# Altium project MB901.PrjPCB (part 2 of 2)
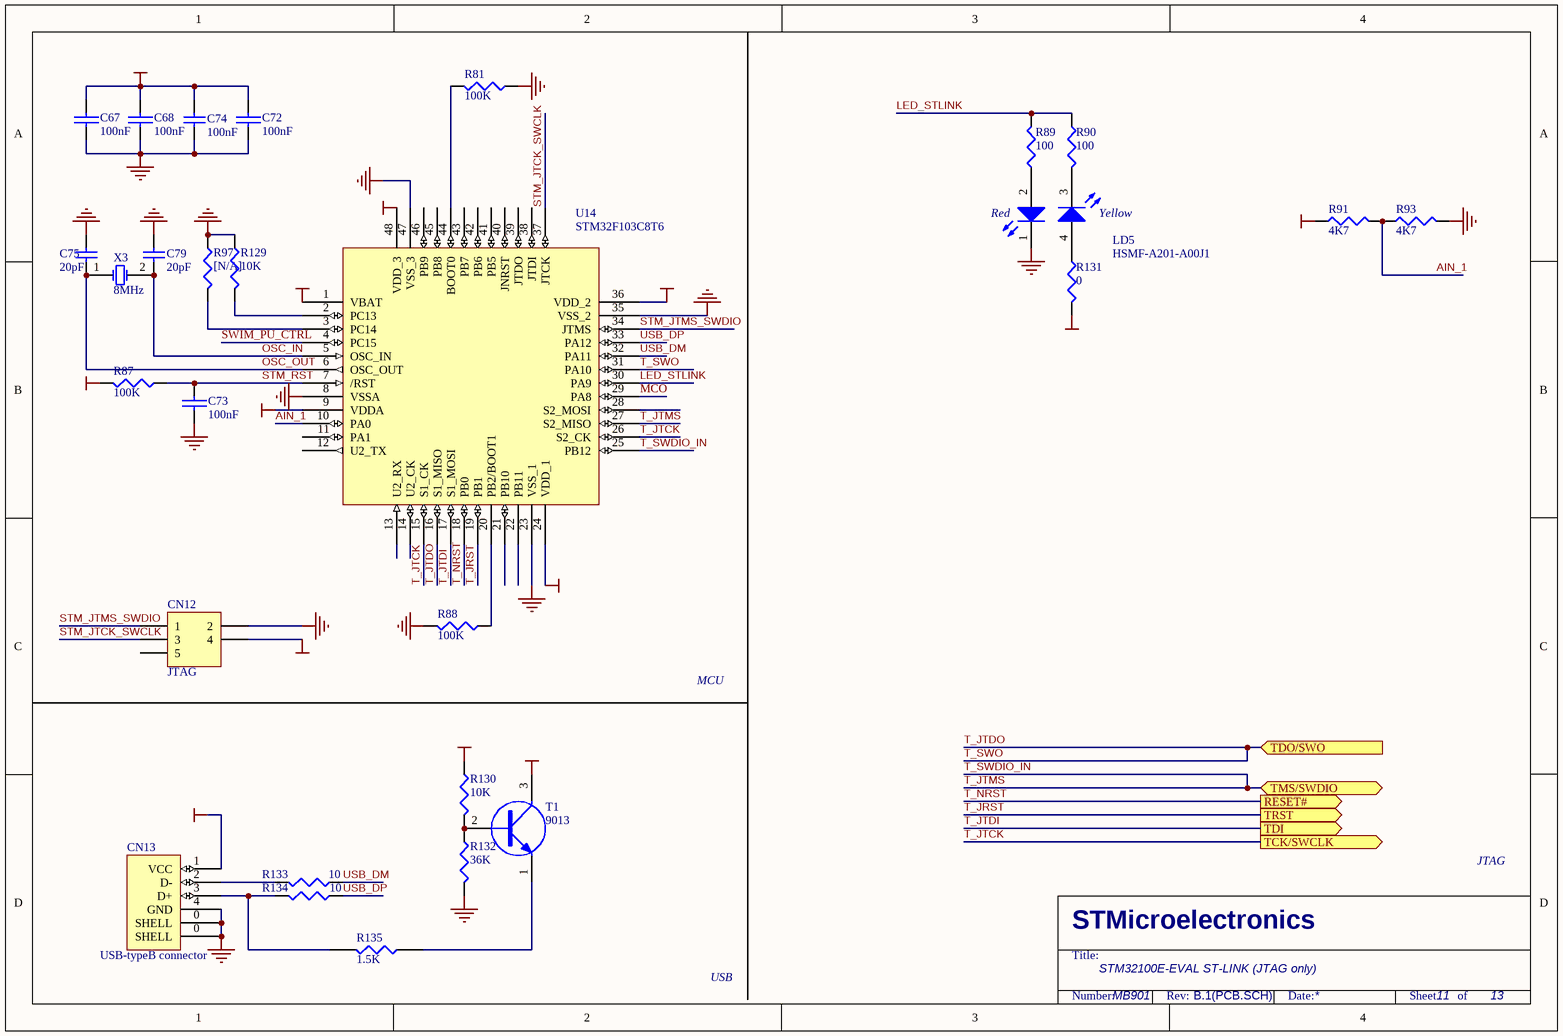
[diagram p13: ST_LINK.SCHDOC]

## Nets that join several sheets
+3V3: MB901 (R83.1 R112.1), Audio (C61.1 R82.1 U11.E3), CEC&IR receiver (7 pins), IO_Peripheral (11 pins), JTAG&SWD (7 pins), LCD&EEPROM&TS (18 pins), MCU (6 pins), MicroSD&SPIFlash (7 pins), MotorCtrl (CN1.28 R10.2), Power (6 pins), RS232&IrDA (13 pins), SRAM&OneNAND (14 pins), ST_LINK (14 pins)
+5V: Audio (C60.1 C62.1 U11.C3 U11.C5), CEC&IR receiver (C20.1 U2.6), LCD&EEPROM&TS (R136.1), MotorCtrl (CN1.25), Power (7 pins), RS232&IrDA (R55.2 U9.8)
D5V: MCU (CN8.49 CN9.19), Power (JP13.4)
GND: Audio (8 pins), CEC&IR receiver (19 pins), IO_Peripheral (26 pins), JTAG&SWD (19 pins), LCD&EEPROM&TS (18 pins), MCU (24 pins), MicroSD&SPIFlash (8 pins), MotorCtrl (27 pins), Power (39 pins), RS232&IrDA (22 pins), SRAM&OneNAND (13 pins), ST_LINK (21 pins)
U5V_ST_LINK: Power (JP13.2), ST_LINK (CN13.1 R130.1)
A0: LCD&EEPROM&TS (CN15.2), MCU (CN8.57 U8.10), SRAM&OneNAND (U3.A3 U4.G2)
A1: MCU (CN8.60 U8.11), SRAM&OneNAND (U3.A4 U4.G3)
A2: MCU (CN8.61 U8.12), SRAM&OneNAND (U3.A5 U4.H4)
A3: MCU (CN8.62 U8.13), SRAM&OneNAND (U3.B3 U4.H5)
A4: MCU (CN8.63 U8.14), SRAM&OneNAND (U3.B4 U4.H2)
A5: MCU (CN8.64 U8.15), SRAM&OneNAND (U3.C3 U4.H3)
A6: MCU (CN9.43 U8.50), SRAM&OneNAND (U3.C4 U4.G6)
A7: MCU (CN9.44 U8.53), SRAM&OneNAND (U3.D4 U4.F4)
A8: MCU (CN9.41 U8.54), SRAM&OneNAND (U3.H2 U4.F6)
A9: MCU (CN9.42 U8.55), SRAM&OneNAND (U3.H3 U4.E6)
A10: MCU (CN9.40 U8.56), SRAM&OneNAND (U3.H4 U4.G5)
A11: MCU (CN9.37 U8.57), SRAM&OneNAND (U3.H5 U4.F5)
A12: MCU (CN9.8 U8.87), SRAM&OneNAND (U3.G3 U4.D2)
A13: MCU (CN9.7 U8.88), SRAM&OneNAND (U3.G4 U4.F2)
A14: MCU (CN9.6 U8.89), SRAM&OneNAND (U3.F3 U4.F1)
A15: MCU (CN9.5 U8.90), SRAM&OneNAND (U3.F4 U4.D4)
A16: MCU (CN9.14 U8.80), SRAM&OneNAND (U3.E4)
A17: MCU (CN9.13 U8.81), SRAM&OneNAND (U3.D3)
A18: MCU (CN9.12 U8.82), SRAM&OneNAND (U3.H1)
A19: MCU (CN8.52 U8.2), SRAM&OneNAND (U3.G2)
A20: MCU (CN8.51 U8.3), SRAM&OneNAND (U3.H6)
D0: LCD&EEPROM&TS (CN15.6), MCU (CN9.32 U8.85), SRAM&OneNAND (U3.B6 U4.D3)
D1: LCD&EEPROM&TS (CN15.7), MCU (CN9.31 U8.86), SRAM&OneNAND (U3.C5 U4.B3)
D2: LCD&EEPROM&TS (CN15.8), MCU (CN8.21 U8.114), SRAM&OneNAND (U3.C6 U4.E3)
D3: LCD&EEPROM&TS (CN15.9), MCU (CN8.22 U8.115), SRAM&OneNAND (U3.D5 U4.C5)
D4: LCD&EEPROM&TS (CN15.10), MCU (CN9.35 U8.58), SRAM&OneNAND (U3.E5 U4.C2)
D5: LCD&EEPROM&TS (CN15.11), MCU (CN9.36 U8.59), SRAM&OneNAND (U3.F5 U4.D5)
D6: LCD&EEPROM&TS (CN15.12), MCU (CN9.33 U8.60), SRAM&OneNAND (U3.F6 U4.D6)
D7: LCD&EEPROM&TS (CN15.13), MCU (CN9.34 U8.63), SRAM&OneNAND (U3.G6 U4.C1)
D8: LCD&EEPROM&TS (CN15.14), MCU (CN9.29 U8.64), SRAM&OneNAND (U3.B1 U4.B2)
D9: LCD&EEPROM&TS (CN15.15), MCU (CN9.28 U8.65), SRAM&OneNAND (U3.C1 U4.B5)
D10: LCD&EEPROM&TS (CN15.16), MCU (CN9.27 U8.66), SRAM&OneNAND (U3.C2 U4.C4)
D11: LCD&EEPROM&TS (CN15.17), MCU (CN9.26 U8.67), SRAM&OneNAND (U3.D2 U4.C3)
D12: LCD&EEPROM&TS (CN15.18), MCU (CN9.25 U8.68), SRAM&OneNAND (U3.E2 U4.B1)
D13: LCD&EEPROM&TS (CN15.19), MCU (CN9.17 U8.77), SRAM&OneNAND (U3.F2 U4.A6)
D14: LCD&EEPROM&TS (CN15.20), MCU (CN9.16 U8.78), SRAM&OneNAND (U3.F1 U4.A3)
D15: LCD&EEPROM&TS (CN15.21), MCU (CN9.15 U8.79), SRAM&OneNAND (U3.G1 U4.D1)
NetC13_2: MCU (JP4.1), MotorCtrl (C13.2 CN1.31 JP2.1)
NetCN1_11: MCU (JP5.3), MotorCtrl (CN1.11)
NetCN11_5: Audio (CN11.5), LCD&EEPROM&TS (U19.11)
NetJP3_2: MCU (JP3.2), MotorCtrl (R8.2)
NetJP4_3: MCU (JP4.3), RS232&IrDA (R33.2)
NetJP5_1: MCU (JP5.1), RS232&IrDA (R43.2)
NetJP6_1: MCU (JP6.1), SRAM&OneNAND (U4.F3)
NetJP6_3: CEC&IR receiver (R39.2), MCU (JP6.3)
NetJP7_2: MCU (JP7.2), RS232&IrDA (U7.16)
NetJP8_2: MCU (JP8.2), RS232&IrDA (U7.20)
NetJP9_1: MCU (JP9.1), RS232&IrDA (R66.2)
NetJP11_2: LCD&EEPROM&TS (R78.1), MCU (JP11.2)
NetR72_1: MB901 (R72.1 R112.2), Audio (U11.E5), LCD&EEPROM&TS (U10.1 U13.5 U19.5)
NetR77_1: MB901 (R77.1 R83.2), Audio (U11.E1), LCD&EEPROM&TS (U10.2 U13.6 U19.4)
PA0: IO_Peripheral (R101.2), MCU (CN8.9 JP4.2 U8.34)
PA1: MCU (CN9.61 U8.35), MotorCtrl (C4.2 CN1.33), RS232&IrDA (R27.2 U5.10)
PA2: MCU (CN9.60 U8.36), MotorCtrl (C5.2 CN1.34), RS232&IrDA (R31.2 U5.11)
PA3: MCU (CN9.58 U8.37), RS232&IrDA (R138.2)
PA4: Audio (C64.2 C66.2), IO_Peripheral (R48.1), MCU (CN9.57 U8.40)
PA5: Audio (JP15.2), MCU (CN9.56 U8.41), MicroSD&SPIFlash (U6.6)
PA6: MCU (CN9.55 JP3.1 U8.42), MicroSD&SPIFlash (R46.1)
PA7: MCU (CN9.54 U8.43), MicroSD&SPIFlash (U6.5), MotorCtrl (CN1.5)
PA8: MCU (CN8.6 TP6.1 U8.100), MotorCtrl (CN1.3)
PA9: MCU (CN8.7 U8.101), MotorCtrl (CN1.7), RS232&IrDA (R50.2 U7.13)
PA11: MCU (CN8.12 U8.103), RS232&IrDA (R100.1 U16.5)
PA12: LCD&EEPROM&TS (R99.1), MCU (CN8.13 U8.104)
PA13: JTAG&SWD (D4.3 RS1.3), MCU (CN8.14 U8.105), ST_LINK (U14.25 U14.27)
PA14: JTAG&SWD (D7.3 RS1.5), MCU (CN8.15 U8.109), ST_LINK (U14.15 U14.26)
PA15: JTAG&SWD (D8.3 RS1.9), MCU (CN8.16 U8.110), ST_LINK (U14.17)
PB0: MCU (CN9.51 U8.46), MotorCtrl (CN1.9)
PB1: MCU (CN9.47 U8.47), MotorCtrl (CN1.13)
PB3: JTAG&SWD (D5.3 RS1.7), MCU (CN8.40 U8.133), ST_LINK (U14.16 U14.31)
PB4: JTAG&SWD (D9.3 RS1.11), MCU (CN8.41 U8.134), MotorCtrl (C57.2 JP12.2), ST_LINK (U14.19)
PB5: MCU (CN8.42 U8.135), MotorCtrl (C6.2 CN1.29)
PB6: CEC&IR receiver (R38.2), MCU (CN8.43 U8.136)
PB8: CEC&IR receiver (R37.2), MCU (CN8.45 U8.139)
PB9: CEC&IR receiver (R35.2), MCU (CN8.46 U8.140)
PB10: MB901 (R77.2), MCU (CN9.24 U8.69)
PB11: MB901 (R72.2), MCU (CN9.23 U8.70)
PB12: MCU (CN9.22 JP11.1 U8.73), MotorCtrl (CN1.21)
PB13: MCU (CN9.21 U8.74), MicroSD&SPIFlash (CN6.5)
PB14: MCU (CN9.20 U8.75), MicroSD&SPIFlash (R24.2)
PB15: MCU (CN9.18 U8.76), MicroSD&SPIFlash (CN6.3)
PC0: MCU (CN9.66 U8.26), MotorCtrl (C12.2 R7.2 R9.2)
PC1: MCU (CN9.65 U8.27), MotorCtrl (C10.2 R6.1)
PC2: MCU (CN9.64 U8.28), MotorCtrl (C9.2 R5.1)
PC3: MCU (CN9.63 U8.29), MotorCtrl (C8.2 R4.1)
PC4: IO_Peripheral (R47.1), MCU (CN9.53 U8.44)
PC5: MCU (CN9.52 U8.45), MotorCtrl (C7.2 R3.2)
PC6: CEC&IR receiver (R1.1), MCU (CN8.2 U8.96)
PC7: LCD&EEPROM&TS (R95.1), MCU (CN8.3 U8.97)
PC8: MCU (CN8.4 U8.98), MotorCtrl (CN1.23)
PC9: MCU (CN8.5 U8.99), RS232&IrDA (R40.2 U9.2 U9.3)
PC10: MCU (CN8.17 U8.111), RS232&IrDA (U16.3)
PC11: MCU (CN8.18 U8.112), RS232&IrDA (R110.2)
PC12: MCU (CN8.20 U8.113), RS232&IrDA (U9.4)
PC13: IO_Peripheral (R103.2), MCU (CN8.56 R11.1 U8.7)
PD2: MCU (CN8.25 JP9.2 U8.116), MotorCtrl (C1.2 CN1.27 JP12.1)
PD3: MCU (CN8.26 U8.117), SRAM&OneNAND (U4.E1)
PD4: LCD&EEPROM&TS (CN15.4), MCU (CN8.27 U8.118), SRAM&OneNAND (U3.A2 U4.B4)
PD5: LCD&EEPROM&TS (CN15.3), MCU (CN8.28 U8.119), SRAM&OneNAND (U3.G5 U4.A1)
PD6: MCU (CN8.29 U8.122), SRAM&OneNAND (R36.2)
PD7: MCU (CN8.31 U8.123), SRAM&OneNAND (R22.2)
PE0: MCU (CN8.47 U8.141), SRAM&OneNAND (U3.A1)
PE1: MCU (CN8.24 U8.142), SRAM&OneNAND (U3.B2)
PE6: MCU (CN8.53 U8.5), MicroSD&SPIFlash (R44.2)
PF6: IO_Peripheral (R76.2), MCU (CN8.65 U8.18)
PF7: IO_Peripheral (R75.2), MCU (CN8.66 U8.19)
PF8: IO_Peripheral (R74.2), MCU (CN8.67 U8.20)
PF9: IO_Peripheral (R73.2), MCU (CN8.68 U8.21)
PF10: MCU (CN9.67 U8.22), SRAM&OneNAND (R28.1)
PF11: MCU (CN9.46 U8.49), MicroSD&SPIFlash (CN6.10)
PG6: MCU (CN9.4 U8.91), MicroSD&SPIFlash (R16.1)
PG7: IO_Peripheral (R105.2), MCU (CN9.3 U8.92)
PG8: IO_Peripheral (R109.2), MCU (CN9.2 U8.93)
PG10: MCU (CN8.33 U8.125), SRAM&OneNAND (R18.2)
PG11: IO_Peripheral (R104.2), MCU (CN8.34 U8.126)
PG12: LCD&EEPROM&TS (R85.2), MCU (CN8.35 U8.127)
PG13: IO_Peripheral (R107.2), MCU (CN8.36 U8.128)
PG14: IO_Peripheral (R106.2), MCU (CN8.37 U8.129)
PG15: IO_Peripheral (R108.2), MCU (CN8.38 U8.132)
RESET#: JTAG&SWD (D6.3 RS1.13), LCD&EEPROM&TS (CN15.5), MCU (7 pins), ST_LINK (U14.18)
